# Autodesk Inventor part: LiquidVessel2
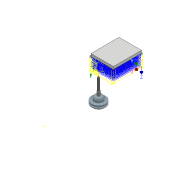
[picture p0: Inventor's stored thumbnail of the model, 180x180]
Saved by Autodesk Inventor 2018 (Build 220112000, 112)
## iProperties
Created: 2018-05
Part Number: LiquidVessel2
Material: Generic
Document SubType Name: Modeling
Designer: arivu
Density: 1 g/cm^3
Appearance: Default
Author: arivu
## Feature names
1. Extrusion1
2. Sweep1
3. TaggingFeature1
## Parameters: d8 = 0, d9 = 175 deg, d10 = 0, d11 = 0
